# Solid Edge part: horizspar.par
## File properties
Author: harmonj5
Template: ansi part.par
Last saved by: harmonj5
Revision: 10
Application: Solid Edge
Accuracy: 0.990
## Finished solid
Body 1: solid body, 6 faces, 12 edges, 8 vertices.
  Faces by surface: plane 6
  Edges by curve: line 12
Bounding box of the edges (mm): 7.620 x 527.050 x 3.302, from (-46.809, 0, 28.3577) to (-39.189, 527.05, 31.6597).
Planar faces by outward normal: +x 1, +y 1, +z 1, -x 1, -y 1, -z 1
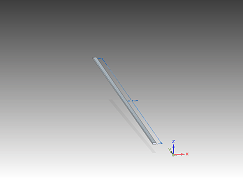
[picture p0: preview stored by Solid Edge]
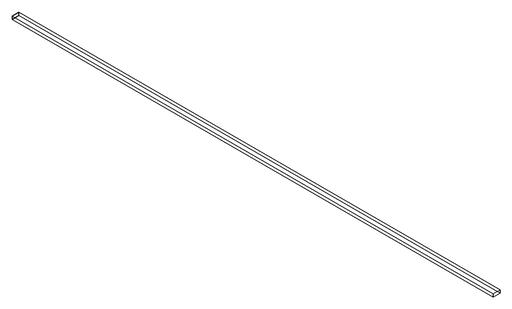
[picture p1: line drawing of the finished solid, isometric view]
